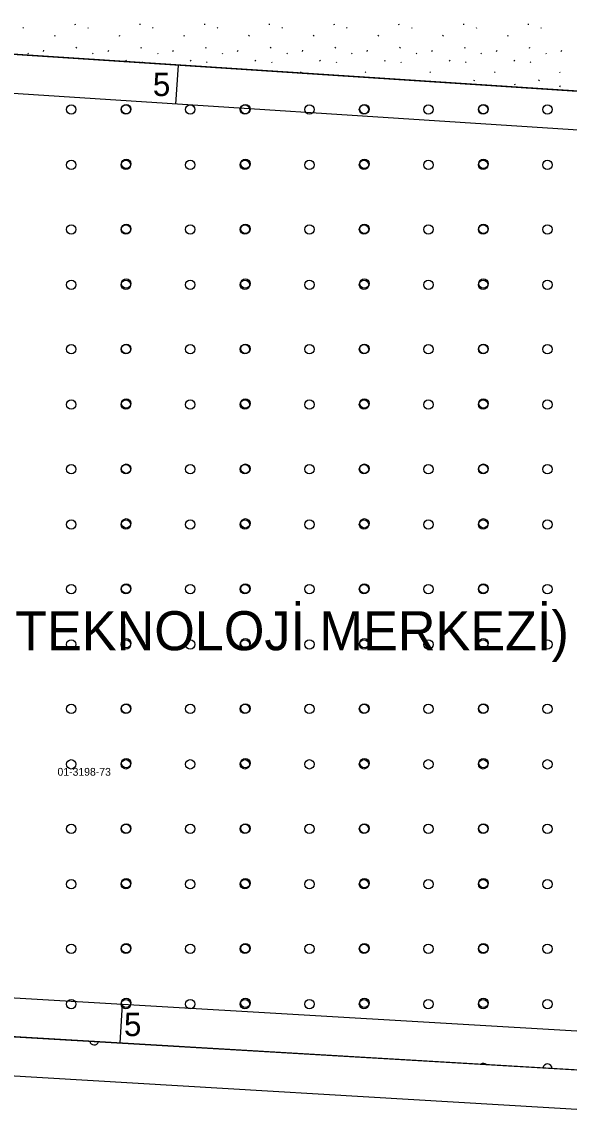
# Model space of a CAD drawing. Extents: x 419396 to 421519, y 4453567 to 4456767.
# Drawn here: x 420779.3 to 420849.4, y 4455422.7 to 4455563.3 of the extents above; entities that cross this region are included whole.
import ezdxf

# ---------------------------------------------------------------- set-up
doc = ezdxf.new("R2010")
doc.units = 0
for name, color, linetype in [('0_KADASTRO', 7, 'Continuous'), ('ADAKENARI1000', 7, 'Continuous'), ('F_YAPI_YAKLAŞMA', 7, 'Continuous'), ('Level 33', 7, 'Continuous'), ('Level 41', 7, 'Continuous'), ('SM_YAPILASMA', 7, 'Continuous')]:
    doc.layers.add(name, color=color, linetype=linetype)

msp = doc.modelspace()

# ---------------------------------------------------------------- linework, layer by layer
at = {"layer": '0_KADASTRO'}
for points in [[(420545.42, 4455447.04), (420561.03, 4455696.59), (420608.27, 4455685.53), (420614.84, 4455734.09), (420621.11, 4455745.07), (420621.38, 4455786.21), (420636.29, 4455823.29), (420701.58, 4455861.23), (420708.62, 4455863.92), (420715.79, 4455864.57), (420723.78, 4455862.78), (420730.13, 4455859.19), (420735, 4455853.4), (420771.9, 4455797.51), (420787.06, 4455778.4), (420884.04, 4455668.02), (420888.93, 4455658.72), (420890.16, 4455653.06), (420890.46, 4455645.52), (420886.58, 4455581.52), (420884.98, 4455552.19), (420718.56, 4455563.04), (420710.4, 4455437.34), (420549.3, 4455446.81)], [(420710.4, 4455437.34), (420718.56, 4455563.04), (420884.98, 4455552.19), (420878.18, 4455427.47)]]:
    msp.add_lwpolyline(points, close=True, dxfattribs=at)
msp.add_lwpolyline([(420652.36, 4454984), (420665.76, 4454988.47), (420707.29, 4455006.2), (420751.48, 4455032.99), (420769.07, 4455051.2), (420804.89, 4455072.7), (420840.78, 4455094.99), (420847.65, 4455100.22), (420853.39, 4455106.67), (420857.79, 4455114.1), (420861.99, 4455130.83), (420878.18, 4455427.47), (420710.4, 4455437.34), (420549.3, 4455446.81)], dxfattribs=at)
at = {"layer": 'ADAKENARI1000'}
for p, q in [((420884.98, 4455552.19), (420718.56, 4455563.04)), ((420710.4, 4455437.34), (420878.18, 4455427.47))]:
    msp.add_line(p, q, dxfattribs=at)
at = {"layer": 'F_YAPI_YAKLAŞMA'}
for p, q in [((420874.73, 4455547.85), (420723.23, 4455557.73)), ((420798.98, 4455552.79), (420799.3, 4455557.78)), ((420715.72, 4455442.04), (420868.47, 4455433.05)), ((420792.09, 4455437.54), (420791.8, 4455432.55)), ((420710.11, 4455432.35), (420867.92, 4455423.06))]:
    msp.add_line(p, q, dxfattribs=at)
at = {"layer": 'Level 33'}
for centre in [(420785.57, 4455552.09), (420792.57, 4455552.09), (420792.62, 4455552.15), (420800.82, 4455552.09), (420807.82, 4455552.09), (420807.88, 4455552.15), (420816.08, 4455552.09), (420823.08, 4455552.09), (420823.14, 4455552.15), (420831.34, 4455552.09), (420838.34, 4455552.09), (420838.39, 4455552.15), (420846.59, 4455552.09), (420785.57, 4455545), (420792.57, 4455545), (420792.62, 4455545.15), (420800.82, 4455545), (420807.82, 4455545), (420807.88, 4455545.15), (420816.08, 4455545), (420823.08, 4455545), (420823.14, 4455545.15), (420831.34, 4455545), (420838.34, 4455545), (420838.39, 4455545.15), (420846.59, 4455545), (420785.57, 4455536.74), (420792.57, 4455536.74), (420792.62, 4455536.8), (420800.82, 4455536.74), (420807.82, 4455536.74), (420807.88, 4455536.8), (420816.08, 4455536.74), (420823.08, 4455536.74), (420823.14, 4455536.8), (420831.34, 4455536.74), (420838.34, 4455536.74), (420838.39, 4455536.8), (420846.59, 4455536.74), (420785.57, 4455529.65), (420792.57, 4455529.65), (420792.62, 4455529.8), (420800.82, 4455529.65), (420807.82, 4455529.65), (420807.88, 4455529.8), (420816.08, 4455529.65), (420823.08, 4455529.65), (420823.14, 4455529.8), (420831.34, 4455529.65), (420838.34, 4455529.65), (420838.39, 4455529.8), (420846.59, 4455529.65), (420785.57, 4455521.39), (420792.57, 4455521.39), (420792.62, 4455521.45), (420800.82, 4455521.39), (420807.82, 4455521.39), (420807.88, 4455521.45), (420816.08, 4455521.39), (420823.08, 4455521.39), (420823.14, 4455521.45), (420831.34, 4455521.39), (420838.34, 4455521.39), (420838.39, 4455521.45), (420846.59, 4455521.39), (420785.57, 4455514.3), (420792.57, 4455514.3), (420792.62, 4455514.45), (420800.82, 4455514.3), (420807.82, 4455514.3), (420807.88, 4455514.45), (420816.08, 4455514.3), (420823.08, 4455514.3), (420823.14, 4455514.45), (420831.34, 4455514.3), (420838.34, 4455514.3), (420838.39, 4455514.45), (420846.59, 4455514.3), (420785.57, 4455506.03), (420792.57, 4455506.03), (420792.62, 4455506.1), (420800.82, 4455506.03), (420807.82, 4455506.03), (420807.88, 4455506.1), (420816.08, 4455506.03), (420823.08, 4455506.03), (420823.14, 4455506.1), (420831.34, 4455506.03), (420838.34, 4455506.03), (420838.39, 4455506.1), (420846.59, 4455506.03), (420785.57, 4455498.95), (420792.57, 4455498.95), (420792.62, 4455499.1), (420800.82, 4455498.95), (420807.82, 4455498.95), (420807.88, 4455499.1), (420816.08, 4455498.95), (420823.08, 4455498.95), (420823.14, 4455499.1), (420831.34, 4455498.95), (420838.34, 4455498.95), (420838.39, 4455499.1), (420846.59, 4455498.95), (420785.57, 4455490.68), (420792.57, 4455490.68), (420792.62, 4455490.74), (420800.82, 4455490.68), (420807.82, 4455490.68), (420807.88, 4455490.74), (420816.08, 4455490.68), (420823.08, 4455490.68), (420823.14, 4455490.74), (420831.34, 4455490.68), (420838.34, 4455490.68), (420838.39, 4455490.74), (420846.59, 4455490.68), (420792.62, 4455483.74), (420807.88, 4455483.74), (420823.14, 4455483.74), (420838.39, 4455483.74), (420785.57, 4455483.59), (420792.57, 4455483.59), (420800.82, 4455483.59), (420807.82, 4455483.59), (420816.08, 4455483.59), (420823.08, 4455483.59), (420831.34, 4455483.59), (420838.34, 4455483.59), (420846.59, 4455483.59), (420785.57, 4455475.33), (420792.57, 4455475.33), (420792.62, 4455475.39), (420800.82, 4455475.33), (420807.82, 4455475.33), (420807.88, 4455475.39), (420816.08, 4455475.33), (420823.08, 4455475.33), (420823.14, 4455475.39), (420831.34, 4455475.33), (420838.34, 4455475.33), (420838.39, 4455475.39), (420846.59, 4455475.33), (420792.62, 4455468.39), (420807.88, 4455468.39), (420823.14, 4455468.39), (420838.39, 4455468.39), (420785.57, 4455468.24), (420792.57, 4455468.24), (420800.82, 4455468.24), (420807.82, 4455468.24), (420816.08, 4455468.24), (420823.08, 4455468.24), (420831.34, 4455468.24), (420838.34, 4455468.24), (420846.59, 4455468.24), (420785.57, 4455459.98), (420792.57, 4455459.98), (420792.62, 4455460.04), (420800.82, 4455459.98), (420807.82, 4455459.98), (420807.88, 4455460.04), (420816.08, 4455459.98), (420823.08, 4455459.98), (420823.14, 4455460.04), (420831.34, 4455459.98), (420838.34, 4455459.98), (420838.39, 4455460.04), (420846.59, 4455459.98), (420785.57, 4455452.89), (420792.57, 4455452.89), (420792.62, 4455453.04), (420800.82, 4455452.89), (420807.82, 4455452.89), (420807.88, 4455453.04), (420816.08, 4455452.89), (420823.08, 4455452.89), (420823.14, 4455453.04), (420831.34, 4455452.89), (420838.34, 4455452.89), (420838.39, 4455453.04), (420846.59, 4455452.89), (420785.57, 4455444.63), (420792.57, 4455444.63), (420792.62, 4455444.69), (420800.82, 4455444.63), (420807.82, 4455444.63), (420807.88, 4455444.69), (420816.08, 4455444.63), (420823.08, 4455444.63), (420823.14, 4455444.69), (420831.34, 4455444.63), (420838.34, 4455444.63), (420838.39, 4455444.69), (420846.59, 4455444.63), (420785.57, 4455437.54), (420792.57, 4455437.54), (420792.62, 4455437.69), (420800.82, 4455437.54), (420807.82, 4455437.54), (420807.88, 4455437.69), (420816.08, 4455437.54), (420823.08, 4455437.54), (420823.14, 4455437.69), (420831.34, 4455437.54), (420838.34, 4455437.54), (420838.39, 4455437.69), (420846.59, 4455437.54)]:
    msp.add_circle(centre, 0.6, dxfattribs=at)
for centre, start, end in [((420788.52, 4455432.92), 193.9696, 339.2952), ((420838.39, 4455429.34), 48.432, 124.8327), ((420838.34, 4455429.27), 60.3062, 112.9586), ((420846.59, 4455429.27), 1.675, 171.5898)]:
    msp.add_arc(centre, 0.6, start, end, dxfattribs=at)
at = {"layer": 'Level 41'}
for p, q in [((420779.39, 4455562.61), (420779.46, 4455562.5)), ((420786.05, 4455563.08), (420786.07, 4455562.92)), ((420787.68, 4455562.61), (420787.75, 4455562.5)), ((420794.35, 4455563.08), (420794.36, 4455562.92)), ((420795.98, 4455562.61), (420796.05, 4455562.5)), ((420802.64, 4455563.08), (420802.66, 4455562.92)), ((420804.27, 4455562.61), (420804.34, 4455562.5)), ((420810.93, 4455563.08), (420810.95, 4455562.92)), ((420812.56, 4455562.61), (420812.63, 4455562.5)), ((420819.22, 4455563.08), (420819.24, 4455562.92)), ((420820.85, 4455562.61), (420820.92, 4455562.5)), ((420827.52, 4455563.08), (420827.54, 4455562.92)), ((420829.15, 4455562.61), (420829.22, 4455562.5)), ((420835.81, 4455563.08), (420835.83, 4455562.92)), ((420837.44, 4455562.61), (420837.51, 4455562.5)), ((420844.1, 4455563.08), (420844.12, 4455562.92)), ((420845.73, 4455562.61), (420845.8, 4455562.5)), ((420783.45, 4455561.46), (420783.52, 4455561.62)), ((420791.74, 4455561.46), (420791.81, 4455561.62)), ((420800.03, 4455561.46), (420800.1, 4455561.62)), ((420808.32, 4455561.46), (420808.4, 4455561.62)), ((420816.62, 4455561.46), (420816.69, 4455561.62)), ((420824.91, 4455561.46), (420824.98, 4455561.62)), ((420833.2, 4455561.46), (420833.28, 4455561.62)), ((420841.5, 4455561.46), (420841.57, 4455561.62)), ((420780.02, 4455559.32), (420780.09, 4455559.21)), ((420782.01, 4455559.52), (420782.08, 4455559.68)), ((420786.22, 4455559.93), (420786.29, 4455560.09)), ((420788.31, 4455559.32), (420788.38, 4455559.21)), ((420790.3, 4455559.52), (420790.37, 4455559.68)), ((420794.51, 4455559.93), (420794.58, 4455560.09)), ((420796.61, 4455559.32), (420796.68, 4455559.21)), ((420798.59, 4455559.52), (420798.66, 4455559.68)), ((420802.8, 4455559.93), (420802.87, 4455560.09)), ((420804.9, 4455559.32), (420804.97, 4455559.21)), ((420806.89, 4455559.52), (420806.96, 4455559.68)), ((420811.1, 4455559.93), (420811.17, 4455560.09)), ((420813.19, 4455559.32), (420813.26, 4455559.21)), ((420815.18, 4455559.52), (420815.25, 4455559.68)), ((420819.39, 4455559.93), (420819.46, 4455560.09)), ((420821.48, 4455559.32), (420821.56, 4455559.21)), ((420823.47, 4455559.52), (420823.54, 4455559.68)), ((420827.68, 4455559.93), (420827.75, 4455560.09)), ((420829.78, 4455559.32), (420829.85, 4455559.21)), ((420831.77, 4455559.52), (420831.84, 4455559.68)), ((420835.98, 4455559.93), (420836.05, 4455560.09)), ((420838.07, 4455559.32), (420838.14, 4455559.21)), ((420840.06, 4455559.52), (420840.13, 4455559.68)), ((420844.27, 4455559.93), (420844.34, 4455560.09)), ((420846.36, 4455559.32), (420846.43, 4455559.21)), ((420848.35, 4455559.52), (420848.42, 4455559.68)), ((420792.52, 4455558.39), (420792.59, 4455558.28)), ((420794.62, 4455558.19), (420794.69, 4455558.09)), ((420800.81, 4455558.39), (420800.88, 4455558.28)), ((420802.91, 4455558.19), (420802.98, 4455558.09)), ((420809.11, 4455558.39), (420809.18, 4455558.28)), ((420811.21, 4455558.19), (420811.28, 4455558.09)), ((420817.4, 4455558.39), (420817.47, 4455558.28)), ((420819.5, 4455558.19), (420819.57, 4455558.09)), ((420825.69, 4455558.39), (420825.76, 4455558.28)), ((420827.79, 4455558.19), (420827.86, 4455558.09)), ((420833.99, 4455558.39), (420834.06, 4455558.28)), ((420836.08, 4455558.19), (420836.16, 4455558.09)), ((420842.28, 4455558.39), (420842.35, 4455558.28)), ((420844.38, 4455558.19), (420844.45, 4455558.09)), ((420814.94, 4455556.93), (420815.01, 4455556.83)), ((420823.24, 4455556.93), (420823.31, 4455556.83)), ((420831.53, 4455556.93), (420831.6, 4455556.83)), ((420839.82, 4455556.93), (420839.89, 4455556.83)), ((420848.12, 4455556.93), (420848.19, 4455556.83)), ((420828.93, 4455555.84), (420828.96, 4455555.9)), ((420837.18, 4455555.74), (420837.25, 4455555.9)), ((420839.93, 4455555.13), (420839.95, 4455555.17)), ((420842.35, 4455555.36), (420842.42, 4455555.25)), ((420845.47, 4455555.74), (420845.55, 4455555.9)), ((420848.17, 4455555.01), (420848.25, 4455555.17))]:
    msp.add_line(p, q, dxfattribs=at)

# ---------------------------------------------------------------- texts
at = {"layer": '0_KADASTRO'}
msp.add_text('01-3198-73', height=1, dxfattribs=at).set_placement((420783.81, 4455466.78))
at = {"layer": 'F_YAPI_YAKLAŞMA'}
for p in [(420796.03, 4455553.81), (420792.33, 4455433.44)]:
    msp.add_text('5', height=3, dxfattribs=at).set_placement(p)
at = {"layer": 'SM_YAPILASMA'}
msp.add_text('(BİLİM VE TEKNOLOJİ MERKEZİ)', height=5, dxfattribs=at).set_placement((420746.05, 4455482.85))

doc.saveas('drawing.dxf')
